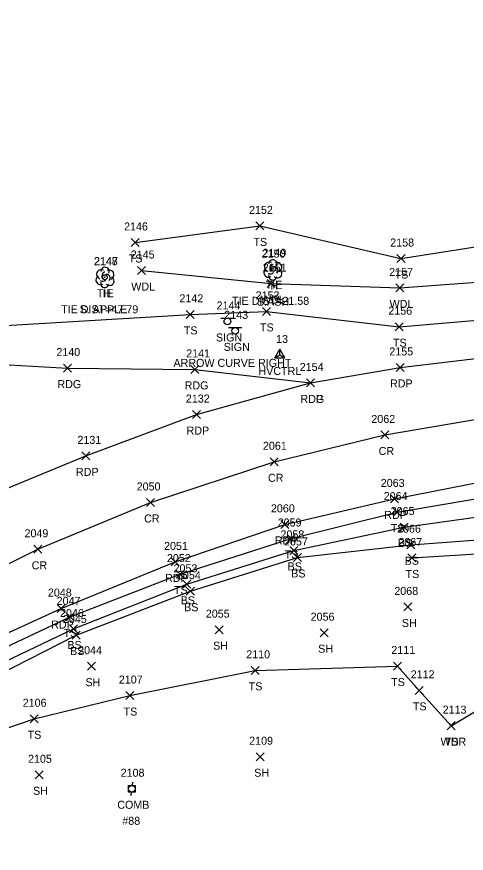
# Model space of a CAD drawing. Extents: x 1699408 to 1700423, y 840176 to 841410.
# Drawn here: x 1699525 to 1699637.2, y 840195 to 840403.9 of the extents above; entities that cross this region are included whole.
import ezdxf

# ---------------------------------------------------------------- set-up
doc = ezdxf.new("R2010")
doc.units = 0
for name, color, linetype in [('C_A', 7, 'Continuous'), ('C_C', 7, 'Continuous'), ('C_I', 7, 'Continuous'), ('CBP', 7, 'Continuous'), ('CPSM', 7, 'Continuous'), ('L_A', 7, 'Continuous'), ('L_C', 7, 'Continuous'), ('L_I', 7, 'Continuous'), ('L_TIC', 7, 'Continuous'), ('LAWA', 7, 'Continuous'), ('LELB', 7, 'Continuous'), ('LTD', 7, 'Continuous'), ('P_A', 7, 'Continuous'), ('P_I', 7, 'Continuous'), ('P_TIC', 7, 'Continuous'), ('PET', 7, 'Continuous'), ('PEU', 7, 'Continuous'), ('PRC', 7, 'Continuous'), ('S_A', 7, 'Continuous'), ('S_C', 7, 'Continuous'), ('S_I', 7, 'Continuous'), ('SSGN', 7, 'Continuous'), ('U_A', 7, 'Continuous'), ('U_C', 7, 'Continuous'), ('U_I', 7, 'Continuous'), ('UP', 7, 'Continuous')]:
    doc.layers.add(name, color=color, linetype=linetype)

msp = doc.modelspace()

# ---------------------------------------------------------------- linework, layer by layer
at = {"layer": 'CBP'}
for centre, radius in [((1699589.01, 840340.96), 0.625), ((1699589.01, 840340.96), 0.0833), ((1699546.93, 840338.86), 0.625), ((1699546.93, 840338.86), 0.0833)]:
    msp.add_circle(centre, radius, dxfattribs=at)
at = {"layer": 'CPSM'}
for p, q in [((1699589.35, 840318.72), (1699590.6, 840320.89)), ((1699589.35, 840318.72), (1699590.6, 840319.44)), ((1699591.85, 840318.72), (1699590.6, 840320.89)), ((1699590.6, 840319.44), (1699590.6, 840320.89)), ((1699590.6, 840319.44), (1699590.6, 840319.44)), ((1699590.6, 840319.44), (1699591.85, 840318.72)), ((1699589.35, 840318.72), (1699591.85, 840318.72))]:
    msp.add_line(p, q, dxfattribs=at)
at = {"layer": 'L_TIC'}
for points in [[(1699584.63, 840350.68), (1699586.63, 840352.68)], [(1699586.63, 840350.68), (1699584.63, 840352.68)], [(1699553.51, 840346.54), (1699555.51, 840348.54)], [(1699555.51, 840346.54), (1699553.51, 840348.54)], [(1699619.87, 840342.53), (1699621.87, 840344.53)], [(1699621.87, 840342.53), (1699619.87, 840344.53)], [(1699555.13, 840339.53), (1699557.13, 840341.53)], [(1699557.13, 840339.53), (1699555.13, 840341.53)], [(1699587.5, 840336.27), (1699589.5, 840338.27)], [(1699589.5, 840336.27), (1699587.5, 840338.27)], [(1699619.6, 840335.18), (1699621.6, 840337.18)], [(1699621.6, 840335.18), (1699619.6, 840337.18)], [(1699567.26, 840328.58), (1699569.26, 840330.58)], [(1699569.26, 840328.58), (1699567.26, 840330.58)], [(1699586.28, 840329.32), (1699588.28, 840331.32)], [(1699588.28, 840329.32), (1699586.28, 840331.32)], [(1699619.45, 840325.5), (1699621.45, 840327.5)], [(1699621.45, 840325.5), (1699619.45, 840327.5)], [(1699618.93, 840279.17), (1699620.93, 840281.17)], [(1699620.93, 840279.17), (1699618.93, 840281.17)], [(1699620.67, 840275.44), (1699622.67, 840277.44)], [(1699622.67, 840275.44), (1699620.67, 840277.44)], [(1699592.44, 840272.59), (1699594.44, 840274.59)], [(1699594.44, 840272.59), (1699592.44, 840274.59)], [(1699593.13, 840269.62), (1699595.13, 840271.62)], [(1699595.13, 840269.62), (1699593.13, 840271.62)], [(1699622.34, 840271.03), (1699624.34, 840273.03)], [(1699624.34, 840271.03), (1699622.34, 840273.03)], [(1699594.02, 840267.85), (1699596.02, 840269.85)], [(1699596.02, 840267.85), (1699594.02, 840269.85)], [(1699622.59, 840267.72), (1699624.59, 840269.72)], [(1699624.59, 840267.72), (1699622.59, 840269.72)], [(1699564.8, 840263.7), (1699566.8, 840265.7)], [(1699566.8, 840263.7), (1699564.8, 840265.7)], [(1699566.45, 840261.15), (1699568.45, 840263.15)], [(1699568.45, 840261.15), (1699566.45, 840263.15)], [(1699567.3, 840259.42), (1699569.3, 840261.42)], [(1699569.3, 840259.42), (1699567.3, 840261.42)], [(1699621.59, 840255.49), (1699623.59, 840257.49)], [(1699623.59, 840255.49), (1699621.59, 840257.49)], [(1699537.28, 840253.01), (1699539.28, 840255.01)], [(1699539.28, 840253.01), (1699537.28, 840255.01)], [(1699538.18, 840249.98), (1699540.18, 840251.98)], [(1699540.18, 840249.98), (1699538.18, 840251.98)], [(1699538.84, 840248.47), (1699540.84, 840250.47)], [(1699540.84, 840248.47), (1699538.84, 840250.47)], [(1699574.5, 840249.81), (1699576.5, 840251.81)], [(1699576.5, 840249.81), (1699574.5, 840251.81)], [(1699600.72, 840249.05), (1699602.72, 840251.05)], [(1699602.72, 840249.05), (1699600.72, 840251.05)], [(1699542.64, 840240.68), (1699544.64, 840242.68)], [(1699544.64, 840240.68), (1699542.64, 840242.68)], [(1699619, 840240.73), (1699621, 840242.73)], [(1699621, 840240.73), (1699619, 840242.73)], [(1699583.46, 840239.65), (1699585.46, 840241.65)], [(1699585.46, 840239.65), (1699583.46, 840241.65)], [(1699624.43, 840234.65), (1699626.43, 840236.65)], [(1699626.43, 840234.65), (1699624.43, 840236.65)], [(1699552.24, 840233.35), (1699554.24, 840235.35)], [(1699554.24, 840233.35), (1699552.24, 840235.35)], [(1699528.29, 840227.56), (1699530.29, 840229.56)], [(1699530.29, 840227.56), (1699528.29, 840229.56)], [(1699632.39, 840225.83), (1699634.39, 840227.83)], [(1699634.39, 840225.83), (1699632.39, 840227.83)], [(1699632.39, 840225.83), (1699634.39, 840227.83)], [(1699634.39, 840225.83), (1699632.39, 840227.83)], [(1699584.76, 840218.07), (1699586.76, 840220.07)], [(1699586.76, 840218.07), (1699584.76, 840220.07)], [(1699529.57, 840213.56), (1699531.57, 840215.56)], [(1699531.57, 840213.56), (1699529.57, 840215.56)]]:
    msp.add_lwpolyline(points, dxfattribs=at)
at = {"layer": 'LAWA'}
for points in [[(1699556.13, 840340.53), (1699588.5, 840337.27), (1699620.6, 840336.18), (1699665.74, 840339.57), (1699700.67, 840345.7), (1699729.87, 840346.11), (1699784.06, 840343.1)], [(1699633.39, 840226.83), (1699656.37, 840240.6), (1699684.65, 840244.27), (1699713.47, 840248.67), (1699728.44, 840253.97), (1699747.5, 840258.18), (1699776.61, 840267.9), (1699816.97, 840275.18), (1699846.39, 840276.57)]]:
    msp.add_lwpolyline(points, dxfattribs=at)
at = {"layer": 'LELB'}
for points in [[(1699554.51, 840347.54), (1699585.63, 840351.68), (1699620.87, 840343.53), (1699664.39, 840350.39), (1699700.67, 840345.7)], [(1699479.81, 840326.06), (1699519.34, 840326.61), (1699568.26, 840329.58), (1699587.28, 840330.32), (1699620.45, 840326.5), (1699668.14, 840330.52), (1699701.48, 840332.44), (1699728.48, 840335.43)], [(1699449.32, 840203.24), (1699477.66, 840221.47), (1699508.6, 840240.03), (1699538.28, 840254.01), (1699565.8, 840264.7), (1699593.44, 840273.59), (1699619.93, 840280.17), (1699647.78, 840284.89), (1699680.49, 840289.58), (1699709.99, 840292.62), (1699741.26, 840296.11), (1699773.28, 840299.24), (1699807.33, 840304.54), (1699837.32, 840309.49), (1699840.77, 840304.78), (1699846.98, 840289.91), (1699852.46, 840279.79)], [(1699450.68, 840200.86), (1699478.43, 840220.04), (1699510.71, 840237.45), (1699539.18, 840250.98), (1699567.45, 840262.15), (1699594.13, 840270.62), (1699621.67, 840276.44), (1699649, 840280.25), (1699681.32, 840285.34), (1699711.01, 840288.64), (1699741.71, 840291.52), (1699773.21, 840296.35), (1699808.7, 840300.3), (1699836.43, 840305.42), (1699838.09, 840303.05), (1699840.88, 840298.91), (1699844.69, 840290.05), (1699850.95, 840279.03)], [(1699452.04, 840198.91), (1699479.59, 840217.72), (1699512.19, 840235.39), (1699539.84, 840249.47), (1699568.3, 840260.42), (1699595.02, 840268.85), (1699623.34, 840272.03), (1699650.02, 840274.02), (1699683.39, 840277.43), (1699712.27, 840281.78), (1699743, 840285.37), (1699773.99, 840291.21), (1699809.19, 840296.39), (1699836.05, 840299.39), (1699842.76, 840289.31), (1699848.51, 840278.09)], [(1699623.59, 840268.72), (1699650.55, 840270.46), (1699684.26, 840273.9), (1699713.02, 840278.92), (1699743.28, 840282.61), (1699774.87, 840287.54), (1699810.2, 840292.51), (1699837.06, 840294.28), (1699841.18, 840284.12), (1699846.39, 840276.57)], [(1699456.6, 840194.95), (1699489.75, 840214.55), (1699495.24, 840216.88), (1699529.29, 840228.56), (1699553.24, 840234.35), (1699584.46, 840240.65), (1699620, 840241.73), (1699625.43, 840235.65), (1699633.39, 840226.83)]]:
    msp.add_lwpolyline(points, dxfattribs=at)
at = {"layer": 'LTD'}
for p, q in [((1699588.86, 840340.75), (1699588.86, 840340.75)), ((1699588.86, 840340.75), (1699588.86, 840340.75)), ((1699546.98, 840338.87), (1699546.98, 840338.87)), ((1699546.98, 840338.87), (1699546.98, 840338.87))]:
    msp.add_line(p, q, dxfattribs=at)
for centre in [(1699588.91, 840342.18), (1699547.03, 840340.3)]:
    msp.add_arc(centre, 1.05, 335.5272, 180.9563, dxfattribs=at)
for centre, major_axis, ratio, start_param, end_param in [((1699588.07, 840341.42), (1.21, -0.51), 0.895232, 1.570796, 4.712389), ((1699589.9, 840341.33), (-1.14, -0.48), 0.949671, 1.570796, 4.712389), ((1699546.19, 840339.53), (1.21, -0.51), 0.895232, 1.570796, 4.712389), ((1699546.77, 840339.33), (-0.208, -0.792), 0.645439, 3.141593, 6.283185), ((1699548.02, 840339.45), (-1.14, -0.48), 0.949671, 1.570796, 4.712389), ((1699587.78, 840340.04), (0.58, -1.04), 0.959034, 3.141593, 6.283185), ((1699588.65, 840341.21), (-0.208, -0.792), 0.645439, 3.141593, 6.283185), ((1699589.36, 840340.58), (-0.5, 0.667), 0.989748, 3.141593, 6.283185), ((1699589.86, 840339.92), (-1.09, 0.79), 0.841452, 1.570796, 4.712389), ((1699545.9, 840338.16), (0.58, -1.04), 0.959034, 3.141593, 6.283185), ((1699546.53, 840338.12), (-0.625, -0.083), 0.423636, 0, 3.141593), ((1699547.48, 840338.7), (-0.5, 0.667), 0.989748, 3.141593, 6.283185), ((1699547.98, 840338.03), (-1.09, 0.79), 0.841452, 1.570796, 4.712389), ((1699588.86, 840339.25), (0.26, 1.06), 0.942809, 1.570796, 4.712389), ((1699588.4, 840340), (-0.625, -0.083), 0.423636, 0, 3.141593), ((1699546.98, 840337.37), (0.26, 1.06), 0.942809, 1.570796, 4.712389)]:
    msp.add_ellipse(centre, major_axis=major_axis, ratio=ratio, start_param=start_param, end_param=end_param, dxfattribs=at)
at = {"layer": 'P_TIC'}
for points in [[(1699536.65, 840315.15), (1699538.65, 840317.15)], [(1699538.65, 840315.15), (1699536.65, 840317.15)], [(1699619.64, 840315.32), (1699621.64, 840317.32)], [(1699621.64, 840315.32), (1699619.64, 840317.32)], [(1699568.4, 840314.83), (1699570.4, 840316.83)], [(1699570.4, 840314.83), (1699568.4, 840316.83)], [(1699597.29, 840311.45), (1699599.29, 840313.45)], [(1699599.29, 840311.45), (1699597.29, 840313.45)], [(1699597.29, 840311.45), (1699599.29, 840313.45)], [(1699599.29, 840311.45), (1699597.29, 840313.45)], [(1699568.87, 840303.55), (1699570.87, 840305.55)], [(1699570.87, 840303.55), (1699568.87, 840305.55)], [(1699615.86, 840298.45), (1699617.86, 840300.45)], [(1699617.86, 840298.45), (1699615.86, 840300.45)], [(1699541.26, 840293.23), (1699543.26, 840295.23)], [(1699543.26, 840293.23), (1699541.26, 840295.23)], [(1699588.24, 840291.75), (1699590.24, 840293.75)], [(1699590.24, 840291.75), (1699588.24, 840293.75)], [(1699618.21, 840282.47), (1699620.21, 840284.47)], [(1699620.21, 840282.47), (1699618.21, 840284.47)], [(1699557.33, 840281.59), (1699559.33, 840283.59)], [(1699559.33, 840281.59), (1699557.33, 840283.59)], [(1699590.88, 840276.12), (1699592.88, 840278.12)], [(1699592.88, 840276.12), (1699590.88, 840278.12)], [(1699529.26, 840269.89), (1699531.26, 840271.89)], [(1699531.26, 840269.89), (1699529.26, 840271.89)], [(1699563.51, 840266.73), (1699565.51, 840268.73)], [(1699565.51, 840266.73), (1699563.51, 840268.73)], [(1699535.09, 840255.08), (1699537.09, 840257.08)], [(1699537.09, 840255.08), (1699535.09, 840257.08)]]:
    msp.add_lwpolyline(points, dxfattribs=at)
at = {"layer": 'PET'}
for points in [[(1699430.72, 840228.22), (1699466.92, 840252.65), (1699493.58, 840268.87), (1699501.63, 840273.58), (1699505.33, 840277.49), (1699516.37, 840283.58), (1699542.26, 840294.23), (1699569.87, 840304.55), (1699598.29, 840312.45), (1699620.64, 840316.32), (1699670.9, 840322.33), (1699702.16, 840325.07), (1699741.15, 840329.16), (1699780.55, 840332.75), (1699814.05, 840338.23), (1699848.8, 840345.35), (1699873.3, 840351.35), (1699914.22, 840362.32), (1699930.57, 840367.02), (1699959.45, 840375.82), (1699990.91, 840385.72), (1700021.62, 840396.71), (1700043.81, 840403.93)], [(1699447.11, 840206.16), (1699475.63, 840224.65), (1699506.94, 840242.78), (1699536.09, 840256.08), (1699564.51, 840267.73), (1699591.88, 840277.12), (1699619.21, 840283.47), (1699647.22, 840288.99), (1699679.73, 840293.47), (1699710.33, 840296.95), (1699740.62, 840299.68), (1699772.35, 840302.79), (1699806.37, 840308.43), (1699836.08, 840313.39), (1699858.12, 840318.39), (1699877.08, 840323.18), (1699900.35, 840329.36), (1699935.97, 840340.61), (1699968.58, 840349.28), (1700000.7, 840359.42), (1700031.35, 840369.03)]]:
    msp.add_lwpolyline(points, dxfattribs=at)
at = {"layer": 'PEU'}
msp.add_lwpolyline([(1699479.51, 840316.42), (1699520.13, 840317.16), (1699537.65, 840316.15), (1699569.4, 840315.83), (1699598.29, 840312.45)], dxfattribs=at)
at = {"layer": 'PRC'}
msp.add_lwpolyline([(1699438.11, 840217.33), (1699474.74, 840241.27), (1699500.34, 840255.97), (1699530.26, 840270.89), (1699558.33, 840282.59), (1699589.24, 840292.75), (1699616.86, 840299.45), (1699644.68, 840304.26), (1699678.81, 840308.53), (1699708.26, 840311.1), (1699739.11, 840314.27), (1699770.93, 840317.73), (1699804.23, 840322.43), (1699833.64, 840328), (1699873.5, 840337.02), (1699896.6, 840342.97), (1699933.32, 840353.07), (1699963.1, 840362.17), (1699996.81, 840372.51), (1700026.94, 840382.38)], dxfattribs=at)
at = {"layer": 'SSGN'}
for p, q in [((1699575.9, 840328.66), (1699579.23, 840328.66)), ((1699577.55, 840327.83), (1699577.55, 840327.83)), ((1699577.84, 840326.32), (1699581.17, 840326.32)), ((1699579.48, 840325.48), (1699579.48, 840325.48))]:
    msp.add_line(p, q, dxfattribs=at)
for centre in [(1699577.55, 840327.83), (1699579.48, 840325.48)]:
    msp.add_circle(centre, 0.833, dxfattribs=at)
at = {"layer": 'UP'}
for p, q in [((1699553.94, 840212.74), (1699553.69, 840211.91)), ((1699552.85, 840210.24), (1699552.85, 840211.91)), ((1699552.85, 840211.91), (1699554.52, 840211.91)), ((1699553.69, 840211.07), (1699553.69, 840211.07)), ((1699554.52, 840211.91), (1699554.52, 840210.24)), ((1699554.52, 840210.24), (1699552.85, 840210.24)), ((1699553.44, 840209.41), (1699553.69, 840210.24))]:
    msp.add_line(p, q, dxfattribs=at)
msp.add_circle((1699553.69, 840211.07), 0.833, dxfattribs=at)

# ---------------------------------------------------------------- texts
at = {"layer": 'C_A'}
for s, p in [('TIE', (1699587.09, 840335.96)), ('TIE', (1699545, 840333.86)), ('HVCTRL', (1699585.29, 840314.44))]:
    msp.add_text(s, height=2, dxfattribs=at).set_placement(p)
at = {"layer": 'C_C'}
for s, p in [('TIE DIST=21.58', (1699578.71, 840331.96)), ('TIE DIST=47.79', (1699536.05, 840329.86))]:
    msp.add_text(s, height=2, dxfattribs=at).set_placement(p)
at = {"layer": 'C_I'}
for s, p in [('2149', (1699586.31, 840343.96)), ('2148', (1699544.23, 840341.86)), ('13', (1699589.7, 840322.44))]:
    msp.add_text(s, height=2, dxfattribs=at).set_placement(p)
at = {"layer": 'L_A'}
for s, p in [('TS', (1699584.04, 840346.68)), ('TS', (1699552.92, 840342.54)), ('TS', (1699619.28, 840338.53)), ('WDL', (1699553.55, 840335.53)), ('H', (1699588.29, 840335.75)), ('H', (1699546.42, 840333.87)), ('WDL', (1699585.92, 840332.27)), ('WDL', (1699618.02, 840331.18)), ('TS', (1699566.67, 840324.58)), ('TS', (1699585.69, 840325.32)), ('TS', (1699618.86, 840321.5)), ('TS', (1699618.34, 840275.17)), ('BS', (1699620.11, 840271.44)), ('TS', (1699591.85, 840268.59)), ('BS', (1699621.78, 840267.03)), ('BS', (1699592.57, 840265.62)), ('BS', (1699593.46, 840263.85)), ('TS', (1699622, 840263.72)), ('TS', (1699564.21, 840259.7)), ('BS', (1699565.89, 840257.15)), ('BS', (1699566.74, 840255.42)), ('SH', (1699621.08, 840251.49)), ('TS', (1699536.69, 840249.01)), ('BS', (1699537.62, 840245.98)), ('BS', (1699538.28, 840244.47)), ('SH', (1699573.99, 840245.81)), ('SH', (1699600.2, 840245.05)), ('SH', (1699542.13, 840236.68)), ('TS', (1699618.41, 840236.73)), ('TS', (1699582.87, 840235.65)), ('TS', (1699623.84, 840230.65)), ('TS', (1699551.64, 840229.35)), ('TS', (1699527.7, 840223.56)), ('WDR', (1699630.75, 840221.83)), ('TS', (1699631.8, 840221.83)), ('SH', (1699584.24, 840214.07)), ('SH', (1699529.06, 840209.56))]:
    msp.add_text(s, height=2, dxfattribs=at).set_placement(p)
at = {"layer": 'L_C'}
for s, p in [('S. APPLE', (1699540.68, 840329.87)), ('S.ASH', (1699584.94, 840331.75))]:
    msp.add_text(s, height=2, dxfattribs=at).set_placement(p)
at = {"layer": 'L_I'}
for s, p in [('2152', (1699582.94, 840354.68)), ('2146', (1699551.76, 840350.54)), ('2158', (1699618.18, 840346.53)), ('2145', (1699553.44, 840343.53)), ('2150', (1699586.08, 840343.75)), ('2147', (1699544.29, 840341.87)), ('2151', (1699586.37, 840340.27)), ('2157', (1699617.91, 840339.18)), ('2142', (1699565.57, 840332.58)), ('2153', (1699584.59, 840333.32)), ('2156', (1699617.7, 840329.5)), ('2064', (1699616.55, 840283.17)), ('2065', (1699618.29, 840279.44)), ('2059', (1699590.1, 840276.59)), ('2058', (1699590.79, 840273.62)), ('2066', (1699619.89, 840275.03)), ('2057', (1699591.68, 840271.85)), ('2067', (1699620.21, 840271.72)), ('2052', (1699562.46, 840267.7)), ('2053', (1699564.11, 840265.15)), ('2054', (1699564.96, 840263.42)), ('2068', (1699619.2, 840259.49)), ('2047', (1699534.94, 840257.01)), ('2046', (1699535.78, 840253.98)), ('2045', (1699536.5, 840252.47)), ('2055', (1699572.16, 840253.81)), ('2056', (1699598.32, 840253.05)), ('2044', (1699540.3, 840244.68)), ('2111', (1699618.45, 840244.73)), ('2110', (1699582.25, 840243.65)), ('2112', (1699623.3, 840238.65)), ('2107', (1699550.46, 840237.35)), ('2106', (1699526.47, 840231.56)), ('2113', (1699631.26, 840229.83)), ('2113', (1699631.26, 840229.83)), ('2109', (1699582.98, 840222.07)), ('2105', (1699527.8, 840217.56))]:
    msp.add_text(s, height=2, dxfattribs=at).set_placement(p)
at = {"layer": 'P_A'}
for s, p in [('RDG', (1699535.13, 840311.15)), ('RDP', (1699618.13, 840311.32)), ('RDG', (1699566.88, 840310.83)), ('RDG', (1699595.78, 840307.45)), ('RDP', (1699595.78, 840307.45)), ('RDP', (1699567.36, 840299.55)), ('CR', (1699615.29, 840294.45)), ('RDP', (1699539.75, 840289.23)), ('CR', (1699587.67, 840287.75)), ('CR', (1699556.77, 840277.59)), ('RDP', (1699616.7, 840278.47)), ('RDP', (1699589.37, 840272.12)), ('CR', (1699528.7, 840265.89)), ('RDP', (1699561.99, 840262.73)), ('RDP', (1699533.57, 840251.08))]:
    msp.add_text(s, height=2, dxfattribs=at).set_placement(p)
at = {"layer": 'P_I'}
for s, p in [('2155', (1699617.95, 840319.32)), ('2140', (1699534.87, 840319.15)), ('2141', (1699567.27, 840318.83)), ('2154', (1699595.6, 840315.45)), ('2154', (1699595.6, 840315.45)), ('2132', (1699567.18, 840307.55)), ('2062', (1699613.47, 840302.45)), ('2131', (1699540.13, 840297.23)), ('2061', (1699586.42, 840295.75)), ('2063', (1699615.82, 840286.47)), ('2050', (1699554.91, 840285.59)), ('2060', (1699588.41, 840280.12)), ('2049', (1699526.92, 840273.89)), ('2051', (1699561.74, 840270.73)), ('2048', (1699532.75, 840259.08))]:
    msp.add_text(s, height=2, dxfattribs=at).set_placement(p)
at = {"layer": 'S_A'}
for p in [(1699574.69, 840322.81), (1699576.62, 840320.46)]:
    msp.add_text('SIGN', height=2, dxfattribs=at).set_placement(p)
at = {"layer": 'S_C'}
msp.add_text('ARROW CURVE RIGHT', height=2, dxfattribs=at).set_placement((1699564.09, 840316.46))
at = {"layer": 'S_I'}
for s, p in [('2144', (1699574.84, 840330.81)), ('2143', (1699576.77, 840328.46))]:
    msp.add_text(s, height=2, dxfattribs=at).set_placement(p)
at = {"layer": 'U_A'}
msp.add_text('COMB', height=2, dxfattribs=at).set_placement((1699550.07, 840206.07))
at = {"layer": 'U_C'}
msp.add_text('#88', height=2, dxfattribs=at).set_placement((1699551.32, 840202.07))
at = {"layer": 'U_I'}
msp.add_text('2108', height=2, dxfattribs=at).set_placement((1699550.91, 840214.07))

doc.saveas('drawing.dxf')
